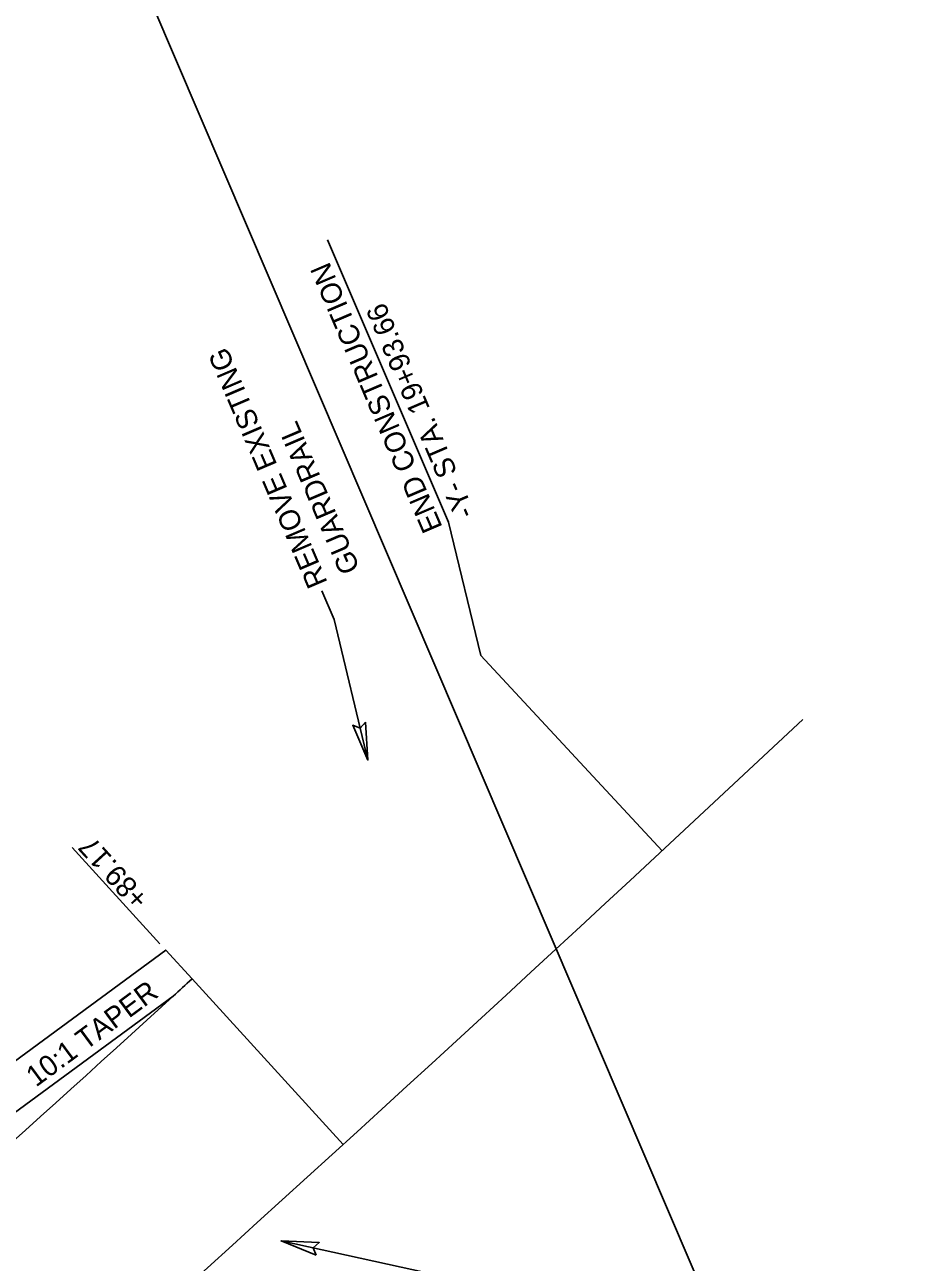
# Model space of a CAD drawing. Extents: x 1550950 to 1552827, y 809595 to 812050.
# Drawn here: x 1551892.9 to 1552108, y 810831.5 to 811129.6 of the extents above; entities that cross this region are included whole.
import ezdxf

# ---------------------------------------------------------------- set-up
doc = ezdxf.new("R2010")
doc.units = 0
for name, color, linetype in [('_CIVIL_CONSTRUCTION', 7, 'Continuous'), ('Draft_Plan_Labels', 7, 'Continuous'), ('Drop Inlet Box Type B 36 Dia-Bottom CELL', 7, 'Continuous'), ('Drop Inlet Grate 2 Narrow Slot and Flat Grates 840 29 36 Dia BD Apron-Top CELL', 7, 'Continuous'), ('Drop Inlet Grate 2 Narrow Slot and Flat Grates 840 29 36 Dia BD CELL', 7, 'Continuous'), ('Drop Inlet Grate 2 Narrow Slot and Flat Grates 840 29 36 Dia TB-Top CELL', 7, 'Continuous'), ('Drop Inlet Grate 3 Narrow Slot and Flat Grates 840 29 48 Dia-Top CELL', 7, 'Continuous'), ('P_HYD_Ditch_Flow_Arrow', 7, 'Continuous'), ('V Ditch Special Lateral with PSRM Detail CELL', 7, 'Continuous')]:
    doc.layers.add(name, color=color, linetype=linetype)

msp = doc.modelspace()

# ---------------------------------------------------------------- linework, layer by layer
at = {"layer": '_CIVIL_CONSTRUCTION'}
msp.add_line((1551925.48, 810908.22), (1551904.35, 810931.37), dxfattribs=at)
at = {"layer": 'Draft_Plan_Labels'}
for points in [[(1552002.79, 810977.64), (1551995.01, 811009.77), (1551965.92, 811077.74)], [(1551975.64, 810952.43), (1551967.45, 810986.29), (1551964.49, 810993.21)], [(1552018.83, 810814.76), (1552015.14, 810823.38), (1551954.69, 810836.6)]]:
    msp.add_lwpolyline(points, dxfattribs=at)
at = {"layer": 'Drop Inlet Box Type B 36 Dia-Bottom CELL'}
for p, q in [((1551834.13, 810838.5), (1551926.9, 810906.66)), ((1551926.9, 810906.66), (1551933.24, 810899.72))]:
    msp.add_line(p, q, dxfattribs=at)
at = {"layer": 'Drop Inlet Grate 2 Narrow Slot and Flat Grates 840 29 36 Dia BD Apron-Top CELL'}
msp.add_line((1552002.79, 810977.64), (1552046.49, 810930.61), dxfattribs=at)
at = {"layer": 'Drop Inlet Grate 2 Narrow Slot and Flat Grates 840 29 36 Dia BD CELL'}
msp.add_lwpolyline([(1551862.14, 809937.08), (1551252.51, 811362.16), (1551737.49, 811569.62), (1552347.13, 810144.54)], close=True, dxfattribs=at)
msp.add_arc((1554524.17, 811845.14), 2911.5, 194.24112, 221.47505, dxfattribs=at)
at = {"layer": 'Drop Inlet Grate 2 Narrow Slot and Flat Grates 840 29 36 Dia TB-Top CELL'}
for points in [[(1551975.03, 810961.55), (1551975.64, 810952.43), (1551971.96, 810960.85), (1551973.79, 810960.11)], [(1551963.16, 810833.16), (1551954.69, 810836.6), (1551963.88, 810836.23), (1551962.41, 810834.91)]]:
    msp.add_lwpolyline(points, close=True, dxfattribs=at)
at = {"layer": 'Drop Inlet Grate 3 Narrow Slot and Flat Grates 840 29 48 Dia-Top CELL'}
msp.add_line((1551928.66, 810895.54), (1551831.98, 810824.51), dxfattribs=at)
msp.add_lwpolyline([(1551834.13, 810838.5), (1551926.9, 810906.66), (1551933.24, 810899.72)], dxfattribs=at)
msp.add_arc((1544245.73, 819324.67), 11405.16, 312.348346, 312.379469, dxfattribs=at)
at = {"layer": 'P_HYD_Ditch_Flow_Arrow'}
msp.add_line((1551933.24, 810899.72), (1551969.63, 810859.83), dxfattribs=at)
msp.add_arc((1554524.17, 811845.14), 2917, 194.24112, 221.47505, dxfattribs=at)
at = {"layer": 'V Ditch Special Lateral with PSRM Detail CELL'}
msp.add_line((1551831.98, 810824.51), (1551928.66, 810895.54), dxfattribs=at)
for centre, radius, start, end in [((1554524.17, 811845.14), 2906, 194.24112, 210.67194), ((1554524.17, 811845.14), 2928, 194.24112, 210.67194), ((1544245.73, 819324.67), 11459.16, 307.933611, 313.133611), ((1544245.73, 819324.67), 11405.16, 310.795027, 312.379469)]:
    msp.add_arc(centre, radius, start, end, dxfattribs=at)

# ---------------------------------------------------------------- texts
at = {"layer": '_CIVIL_CONSTRUCTION'}
msp.add_text('+89.17', height=5, rotation=132.3652, dxfattribs=at).set_placement((1551923.1, 810919.3))
at = {"layer": 'Draft_Plan_Labels'}
for s, rotation, p in [('END CONSTRUCTION', 113.1736, (1551993.67, 811008.54)), ('-Y- STA. 19+93.66', 113.1736, (1552001.48, 811011.88)), ('REMOVE EXISTING', 113.1736, (1551965.97, 810995.22)), ('GUARDRAIL', 113.1736, (1551973.78, 810998.57)), ('10:1 TAPER', 36.5182, (1551895.64, 810873.54))]:
    msp.add_text(s, height=5, rotation=rotation, dxfattribs=at).set_placement(p)

doc.saveas('drawing.dxf')
